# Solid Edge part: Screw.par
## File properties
Title: Screw
Author: Robert a Rhodes jr
Template: Normal.par
Last saved by: Cadcim
Revision: 8
Application: Solid Edge
Material: aluminum
Accuracy: 0.99
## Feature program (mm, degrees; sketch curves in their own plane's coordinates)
sketch for "unnamed Protrusion 1" plane through (0, 0, 0) normal (0, -1, 0) x-axis (1, 0, 0)
  circle centre (0, 0) radius 12.5
extrude "unnamed Protrusion 1" add finite 25 along +normal
sketch for "ExtrudedProtrusion_2" plane through (0, -25, 0) normal (0, -1, 0) x-axis (1, 0, 0)
  circle centre (0, 0) radius 10
extrude "ExtrudedProtrusion_2" add finite 96 along +normal
sketch for "ExtrudedProtrusion_3" plane through (0, -121, 0) normal (0, -1, 0) x-axis (1, 0, 0)
  circle centre (0, 0) radius 6
extrude "ExtrudedProtrusion_3" add finite 4 along +normal
sketch for "ExtrudedProtrusion_4" plane through (0, -125, 0) normal (0, -1, 0) x-axis (1, 0, 0)
  circle centre (0, 0) radius 4
extrude "ExtrudedProtrusion_4" add finite 6 along +normal
sketch for "unnamed RevolvedProtrusion 1" plane through (0, 0, 0) normal (0, 0, 1) x-axis (1, 0, 0)
  line (0, -131) -> (6, -131)
  line (6, -131) -> (6, -141)
  line (6, -141) -> (0, -143.8522)
  line (0, -143.8522) -> (0, -131)
revolve "unnamed RevolvedProtrusion 1" add full turn 360 deg about sketch line (0, -131) -> (0, -106.3065)
sketch for "ExtrudedCutout_1" plane through (0, 0, 0) normal (1, 0, 0) x-axis (0, 1, 0)
  circle centre (-13, 0) radius 5.5
extrude "ExtrudedCutout_1" cut finite 222.1 symmetric
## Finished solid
Body 1: solid body, 12 faces, 12 edges, 1 vertex.
  Faces by surface: cylinder 6, plane 5, cone 1
  Edges by curve: circle 10, intersection 2
Bounding box of the edges (mm): 25.000 x 141.000 x 25.000, from (-12.5, -141, -12.5) to (12.5, 0, 12.5).
Cylindrical faces by radius (mm): R4 x1, R5.5 x1, R6 x2, R10 x1, R12.5 x1
Conical faces (half-angle, radius in mm at the cone's reference point): 64.5754 deg R6 x1
Planar faces by outward normal: +y 2, -y 3
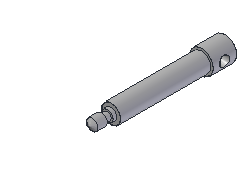
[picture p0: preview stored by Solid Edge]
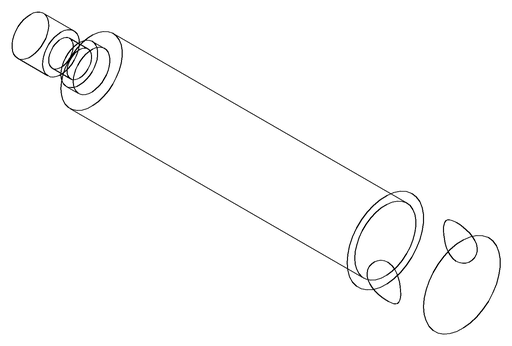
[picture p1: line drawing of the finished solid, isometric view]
